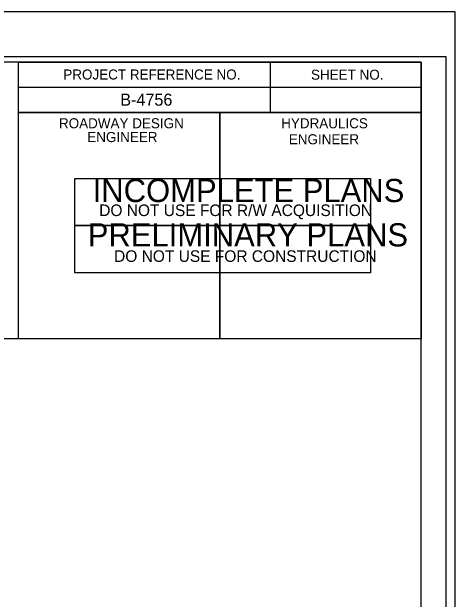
# Model space of a CAD drawing. Extents: x 2431000 to 2534000, y 645879 to 714000.
# Drawn here: x 2464298.6 to 2464519.1, y 662081.3 to 662373.5 of the extents above; entities that cross this region are included whole.
import ezdxf

# ---------------------------------------------------------------- set-up
doc = ezdxf.new("R2010")
doc.units = 0
for name, color, linetype in [('KHA_LOGO', 7, 'Continuous'), ('Old_Level_2', 7, 'Continuous'), ('Prop Dimension', 7, 'Continuous'), ('Prop Dimension Text', 7, 'Continuous'), ('Prop Terminator CELL', 7, 'Continuous'), ('Sheet Clip Boundary CELL', 7, 'Continuous')]:
    doc.layers.add(name, color=color, linetype=linetype)

msp = doc.modelspace()

# ---------------------------------------------------------------- linework, layer by layer
at = {"layer": 'KHA_LOGO'}
for points in [[(2464302.02, 662323.36), (2464402.07, 662323.36), (2464402.07, 662210.86), (2464302.02, 662210.86)], [(2464402.07, 662323.36), (2464502.07, 662323.36), (2464502.07, 662210.86), (2464402.07, 662210.86)]]:
    msp.add_lwpolyline(points, close=True, dxfattribs=at)
at = {"layer": 'Old_Level_2'}
for p, q in [((2464427.07, 662348.41), (2464427.07, 662323.41)), ((2464302.02, 662335.91), (2464502.07, 662335.91))]:
    msp.add_line(p, q, dxfattribs=at)
for points in [[(2464502.07, 662348.46), (2463002.07, 662348.46), (2463002.07, 661298.46), (2464502.07, 661298.46)], [(2464302.02, 662348.46), (2464502.07, 662348.46), (2464502.07, 662323.41), (2464302.02, 662323.41)]]:
    msp.add_lwpolyline(points, close=True, dxfattribs=at)
at = {"layer": 'Prop Dimension'}
msp.add_lwpolyline([(2462835.57, 661273.46), (2464519.07, 661273.46), (2464519.07, 662373.46), (2462835.57, 662373.46)], close=True, dxfattribs=at)
at = {"layer": 'Prop Dimension Text'}
for points in [[(2464329.87, 662267.11), (2464329.87, 662290.61), (2464476.87, 662290.61), (2464476.87, 662267.12)], [(2464329.87, 662243.62), (2464329.87, 662267.11), (2464476.87, 662267.12), (2464476.87, 662243.62)]]:
    msp.add_lwpolyline(points, close=True, dxfattribs=at)
at = {"layer": 'Prop Terminator CELL'}
msp.add_lwpolyline([(2462848.57, 661295.96), (2464514.57, 661295.96), (2464514.57, 662350.96), (2462848.57, 662350.96)], close=True, dxfattribs=at)
at = {"layer": 'Sheet Clip Boundary CELL'}
msp.add_lwpolyline([(2464202.02, 662210.91), (2464302.02, 662210.91), (2464302.02, 662348.46), (2464202.02, 662348.46)], close=True, dxfattribs=at)

# ---------------------------------------------------------------- texts
at = {"layer": 'KHA_LOGO'}
for s, height, p in [('B-4756', 6, (2464352.56, 662326.75)), ('HYDRAULICS', 5, (2464432.52, 662315.51)), ('ENGINEER', 5, (2464436.32, 662307.56))]:
    msp.add_text(s, height=height, dxfattribs=at).set_placement(p)
at = {"layer": 'Old_Level_2'}
for s, height, p in [('PROJECT REFERENCE NO.', 5.0001, (2464324.22, 662339.76)), ('SHEET NO.', 5, (2464447.37, 662339.66)), ('ROADWAY DESIGN', 5.0001, (2464322.07, 662315.51)), ('ENGINEER', 5, (2464336.12, 662308.66))]:
    msp.add_text(s, height=height, dxfattribs=at).set_placement(p)
at = {"layer": 'Prop Dimension Text'}
for s, height, p in [('INCOMPLETE PLANS', 11.52, (2464338.82, 662278.82)), ('DO NOT USE FOR R/W ACQUISITION', 5.76, (2464342.07, 662271.86)), ('PRELIMINARY PLANS', 11.52, (2464336.37, 662256.76)), ('DO NOT USE FOR CONSTRUCTION', 5.76, (2464349.47, 662249.07))]:
    msp.add_text(s, height=height, dxfattribs=at).set_placement(p)

doc.saveas('drawing.dxf')
